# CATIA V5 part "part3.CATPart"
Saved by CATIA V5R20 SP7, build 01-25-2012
Part number: squelette pied droit
Publications: "Plan.5", "Plan.7", "Plan.6", "Point.5"
Bounding box of the stored display mesh (mm): x -55.52 to 20.848, y -105 to -85, z -64.407 to 30.332
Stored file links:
  F:\Travaux\Modélisations\CFAO_2011\CFAO_2011_MMS\CFAO_2011_MMS_DONE\CFAO_2011_MMS_jboiteux\Catia\part3.CATPart
  U:\finthinkmotion\stepper.CATProduct
  F:\Travaux\Modélisations\CFAO_2011\CFAO_2011_MMS\CFAO_2011_MMS_DONE\CFAO_2011_MMS_jboiteux\Catia\Part1.CATPart
  F:\Travaux\Modélisations\CFAO_2011\CFAO_2011_MMS\CFAO_2011_MMS_DONE\CFAO_2011_MMS_jboiteux\Catia\squelette corps.CATPart
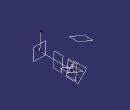
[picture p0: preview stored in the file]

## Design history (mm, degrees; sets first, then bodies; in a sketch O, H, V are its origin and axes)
Parameters
  longueurpied = 108 mm
Set1
  Plane1: linked copy from another document
  Point1: linked copy from another document
  Plane2: linked copy from another document
  Plane3: linked copy from another document
Body1 (main body)
  Line1: stored without definition
  Point2: stored without definition
  Line2: stored without definition
  Line3: type PtDir, RefPoint Point2, Direction Line2, Start -5, End 5
  Point3: stored without definition
  Plane4: type OffsetPt, RefPlane zx-plane, RefPoint Point3
  Point4: stored without definition
  Line4: stored without definition
  Line5: type PtDir, RefPoint Point4, Direction Line4, Start 0, End -108 {= -longueurpied}
  Point5: type OnCurve, Support Line5, Length 13
  Line6: type Angle, RefPoint Point5, Curve Line5, Support Plane1, Start 0, End -10, Angle 90
  Point6: (0, 0, 0), relative to vertex of Line6
  Line7: type Angle, RefPoint Point1, Curve Line5, Support Plane2, Start 0, End 30, Angle 90
  Plane5: type 2Lines, Element1 Line5, Element2 Line6
  Plane6: type Normal, Curve Line5, RefPoint vertex of Line5
  Plane7: type OffsetPt, RefPlane Plane5, RefPoint Point5
  Plane8: type OffsetPt, RefPlane Plane3, RefPoint Point5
